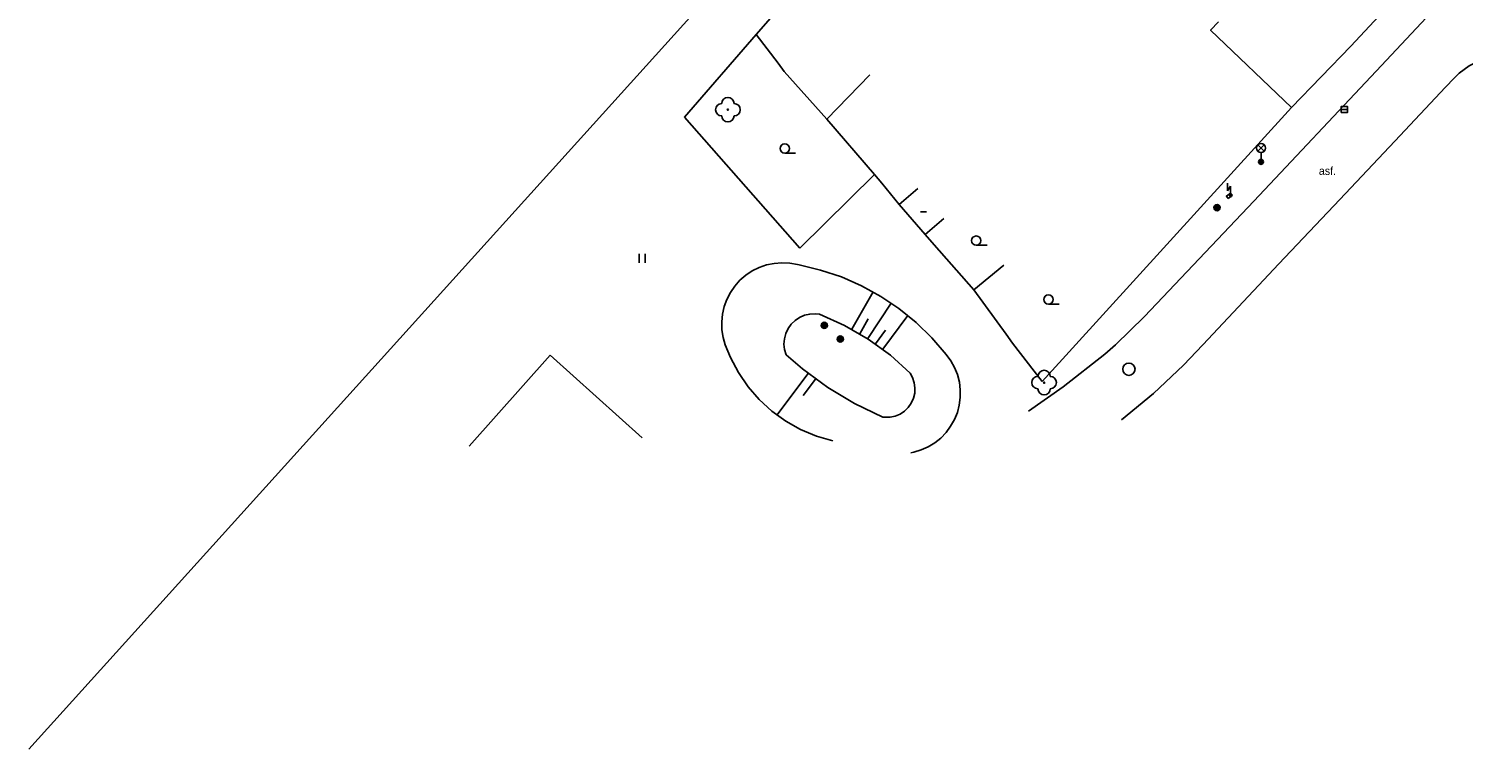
# Model space of a CAD drawing. Extents: x -539244 to -537359, y -1183785 to -1181851.
# Drawn here: x -538323 to -538206.4, y -1183785.5 to -1183727 of the extents above; entities that cross this region are included whole.
import ezdxf

# ---------------------------------------------------------------- set-up
doc = ezdxf.new("R2010")
doc.units = 0
for name, color, linetype in [('Vrstva 10', 7, 'Continuous'), ('Vrstva 14', 7, 'Continuous'), ('Vrstva 15', 7, 'Continuous'), ('Vrstva 21', 7, 'Continuous'), ('Vrstva 22', 7, 'Continuous'), ('Vrstva 24', 7, 'Continuous'), ('Vrstva 25', 7, 'Continuous'), ('Vrstva 27', 7, 'Continuous'), ('Vrstva 33', 7, 'Continuous'), ('Vrstva 36', 7, 'Continuous'), ('Vrstva 39', 7, 'Continuous'), ('Vrstva 40', 7, 'Continuous'), ('Vrstva 5', 7, 'Continuous'), ('Vrstva 7', 7, 'Continuous'), ('Vrstva 8', 7, 'Continuous')]:
    doc.layers.add(name, color=color, linetype=linetype)

msp = doc.modelspace()

# ---------------------------------------------------------------- linework, layer by layer
at = {"layer": 'Vrstva 10'}
for p, q in [((-538209.433, -1183726.06), (-538213.525, -1183730.418)), ((-538213.525, -1183730.418), (-538223.455, -1183740.964)), ((-538212.008, -1183736.103), (-538207.88, -1183731.704)), ((-538207.88, -1183731.704), (-538207.178, -1183730.974)), ((-538216.465, -1183740.837), (-538212.008, -1183736.103)), ((-538223.455, -1183740.964), (-538232.32, -1183750.334)), ((-538221.409, -1183746.068), (-538216.465, -1183740.837)), ((-538225.531, -1183750.441), (-538221.409, -1183746.068)), ((-538227.595, -1183752.627), (-538225.531, -1183750.441)), ((-538280.61, -1183753.48), (-538287.19, -1183760.86)), ((-538273.13, -1183760.2), (-538280.61, -1183753.48))]:
    msp.add_line(p, q, dxfattribs=at)
for points in [[(-538204.121, -1183729.202), (-538205.076, -1183729.521), (-538205.968, -1183729.987), (-538206.775, -1183730.588), (-538207.178, -1183730.974)], [(-538232.32, -1183750.334), (-538234.677, -1183752.637), (-538235.538, -1183753.4)], [(-538234.188, -1183758.717), (-538231.592, -1183756.593), (-538229.154, -1183754.289), (-538227.595, -1183752.627)], [(-538235.538, -1183753.4), (-538238.924, -1183756.038), (-538241.753, -1183758.022)]]:
    msp.add_lwpolyline(points, dxfattribs=at)
at = {"layer": 'Vrstva 14'}
for points in [[(-538266.38, -1183752.64), (-538266.556, -1183752.034), (-538266.655, -1183751.412), (-538266.673, -1183750.781), (-538266.612, -1183750.153), (-538266.472, -1183749.539), (-538266.256, -1183748.946), (-538265.966, -1183748.386), (-538265.608, -1183747.867), (-538265.187, -1183747.398), (-538264.71, -1183746.985), (-538264.184, -1183746.636), (-538263.619, -1183746.357), (-538263.023, -1183746.151), (-538262.405, -1183746.022), (-538261.777, -1183745.972)], [(-538261.777, -1183745.972), (-538261.147, -1183746.003), (-538260.526, -1183746.112), (-538260.38, -1183746.15)], [(-538260.38, -1183746.15), (-538258.644, -1183746.563), (-538256.952, -1183747.129), (-538255.318, -1183747.845), (-538253.754, -1183748.704), (-538252.273, -1183749.7)], [(-538261.44, -1183753.44), (-538261.566, -1183753.018), (-538261.613, -1183752.581), (-538261.58, -1183752.142), (-538261.469, -1183751.716), (-538261.283, -1183751.318), (-538261.028, -1183750.959), (-538260.712, -1183750.653), (-538260.346, -1183750.409), (-538259.942, -1183750.234), (-538259.513, -1183750.136), (-538259.073, -1183750.117), (-538258.72, -1183750.16)], [(-538258.72, -1183750.16), (-538256.687, -1183751.056), (-538254.762, -1183752.167), (-538252.968, -1183753.478), (-538251.37, -1183754.93)], [(-538252.273, -1183749.7), (-538250.888, -1183750.824), (-538249.609, -1183752.068), (-538248.446, -1183753.421), (-538248.06, -1183753.93)], [(-538265.319, -1183754.896), (-538265.967, -1183753.668), (-538266.38, -1183752.64)], [(-538253.59, -1183758.51), (-538255.881, -1183757.414), (-538258.059, -1183756.107), (-538260.103, -1183754.601), (-538261.44, -1183753.44)], [(-538248.06, -1183753.93), (-538247.755, -1183754.476), (-538247.523, -1183755.057), (-538247.366, -1183755.662), (-538247.288, -1183756.283), (-538247.289, -1183756.908), (-538247.371, -1183757.528), (-538247.531, -1183758.133), (-538247.766, -1183758.712), (-538248.074, -1183759.257), (-538248.448, -1183759.757), (-538248.883, -1183760.207), (-538249.372, -1183760.596), (-538249.907, -1183760.921), (-538250.479, -1183761.174), (-538251.078, -1183761.353), (-538251.31, -1183761.4)], [(-538257.64, -1183760.43), (-538258.975, -1183760.048), (-538260.257, -1183759.515), (-538261.47, -1183758.838), (-538262.596, -1183758.026), (-538263.622, -1183757.09), (-538264.534, -1183756.042), (-538265.319, -1183754.896)], [(-538251.37, -1183754.93), (-538251.162, -1183755.305), (-538251.028, -1183755.712), (-538250.971, -1183756.137), (-538250.994, -1183756.566), (-538251.096, -1183756.982), (-538251.273, -1183757.372), (-538251.52, -1183757.723), (-538251.827, -1183758.022), (-538252.185, -1183758.259), (-538252.58, -1183758.425), (-538252.999, -1183758.516), (-538253.428, -1183758.527), (-538253.59, -1183758.51)]]:
    msp.add_lwpolyline(points, dxfattribs=at)
at = {"layer": 'Vrstva 15'}
for p, q in [((-538256.099, -1183751.366), (-538254.378, -1183748.339)), ((-538254.811, -1183752.135), (-538252.918, -1183749.242)), ((-538255.448, -1183751.739), (-538254.761, -1183750.531)), ((-538253.583, -1183752.995), (-538251.544, -1183750.266)), ((-538254.189, -1183752.554), (-538253.367, -1183751.454)), ((-538259.641, -1183754.969), (-538262.18, -1183758.349)), ((-538259.042, -1183755.42), (-538260.05, -1183756.763))]:
    msp.add_line(p, q, dxfattribs=at)
at = {"layer": 'Vrstva 21'}
for p, q in [((-538263.86, -1183727.43), (-538269.69, -1183734.15)), ((-538269.69, -1183734.15), (-538260.33, -1183744.79)), ((-538260.33, -1183744.79), (-538254.26, -1183738.8))]:
    msp.add_line(p, q, dxfattribs=at)
at = {"layer": 'Vrstva 22'}
for centre in [(-538266.17, -1183733.54), (-538240.48, -1183755.71)]:
    msp.add_circle(centre, 0.05, dxfattribs=at)
for centre, start, end in [((-538266.67, -1183733.54), 90, 270), ((-538266.17, -1183733.04), 0, 180), ((-538265.67, -1183733.54), 270, 90), ((-538266.17, -1183734.04), 180, 0), ((-538240.98, -1183755.71), 90, 270), ((-538240.48, -1183755.21), 0, 180), ((-538239.98, -1183755.71), 270, 90), ((-538240.48, -1183756.21), 180, 0)]:
    msp.add_arc(centre, 0.5, start, end, dxfattribs=at)
at = {"layer": 'Vrstva 24'}
for p, q in [((-538225.581, -1183739.509), (-538225.581, -1183740.135)), ((-538225.581, -1183740.135), (-538225.331, -1183739.76)), ((-538225.331, -1183739.76), (-538225.331, -1183740.635)), ((-538225.441, -1183740.39), (-538225.331, -1183740.635)), ((-538225.331, -1183740.635), (-538225.221, -1183740.39))]:
    msp.add_line(p, q, dxfattribs=at)
msp.add_lwpolyline([(-538225.53, -1183740.75), (-538225.673, -1183740.56), (-538225.343, -1183740.31), (-538225.2, -1183740.5), (-538225.53, -1183740.75)], dxfattribs=at)
at = {"layer": 'Vrstva 25'}
for centre, radius in [((-538226.437, -1183741.494), 0.25), ((-538226.437, -1183741.494), 0.2), ((-538226.437, -1183741.494), 0.15), ((-538226.437, -1183741.494), 0.1), ((-538226.437, -1183741.494), 0.05), ((-538258.34, -1183751.06), 0.25), ((-538258.34, -1183751.06), 0.2), ((-538258.34, -1183751.06), 0.15), ((-538258.34, -1183751.06), 0.1), ((-538258.34, -1183751.06), 0.05), ((-538257.04, -1183752.17), 0.25), ((-538257.04, -1183752.17), 0.2), ((-538257.04, -1183752.17), 0.15), ((-538257.04, -1183752.17), 0.1), ((-538257.04, -1183752.17), 0.05)]:
    msp.add_circle(centre, radius, dxfattribs=at)
at = {"layer": 'Vrstva 27'}
msp.add_line((-538216.349, -1183733.524), (-538215.849, -1183733.524), dxfattribs=at)
msp.add_lwpolyline([(-538216.349, -1183733.774), (-538215.849, -1183733.774), (-538215.849, -1183733.274), (-538216.349, -1183733.274)], close=True, dxfattribs=at)
msp.add_circle((-538233.598, -1183754.62), 0.5, dxfattribs=at)
at = {"layer": 'Vrstva 33'}
for p, q in [((-538223.129, -1183736.921), (-538222.599, -1183736.391)), ((-538223.129, -1183736.391), (-538222.599, -1183736.921)), ((-538222.864, -1183737.031), (-538222.864, -1183737.781))]:
    msp.add_line(p, q, dxfattribs=at)
for centre, radius in [((-538222.864, -1183736.656), 0.375), ((-538222.864, -1183737.781), 0.2), ((-538222.864, -1183737.781), 0.145), ((-538222.864, -1183737.781), 0.0876)]:
    msp.add_circle(centre, radius, dxfattribs=at)
at = {"layer": 'Vrstva 36'}
for p, q in [((-538261.548, -1183737.067), (-538260.673, -1183737.067)), ((-538245.996, -1183744.548), (-538245.121, -1183744.548)), ((-538273.376, -1183745.991), (-538273.376, -1183745.241)), ((-538272.876, -1183745.991), (-538272.876, -1183745.241)), ((-538240.133, -1183749.33), (-538239.258, -1183749.33))]:
    msp.add_line(p, q, dxfattribs=at)
for centre in [(-538261.548, -1183736.692), (-538245.996, -1183744.173), (-538240.133, -1183748.955)]:
    msp.add_circle(centre, 0.375, dxfattribs=at)
at = {"layer": 'Vrstva 39'}
msp.add_line((-538250.528, -1183741.824), (-538250.028, -1183741.824), dxfattribs=at)
at = {"layer": 'Vrstva 5'}
for p, q in [((-538215.568, -1183728.37), (-538212.15, -1183724.72)), ((-538220.4, -1183733.36), (-538215.568, -1183728.37)), ((-538252.25, -1183741.24), (-538250.734, -1183739.935)), ((-538252.25, -1183741.24), (-538250.15, -1183743.68)), ((-538250.15, -1183743.68), (-538248.634, -1183742.375))]:
    msp.add_line(p, q, dxfattribs=at)
msp.add_lwpolyline([(-538226.32, -1183726.41), (-538226.96, -1183727.09), (-538220.4, -1183733.36)], dxfattribs=at)
at = {"layer": 'Vrstva 7'}
for p, q in [((-538263.86, -1183727.43), (-538256.2, -1183718.61)), ((-538322.96, -1183785.49), (-538267.21, -1183723.77)), ((-538262.08, -1183729.76), (-538263.86, -1183727.43)), ((-538258.12, -1183734.31), (-538261.61, -1183730.45)), ((-538258.12, -1183734.31), (-538254.639, -1183730.721)), ((-538254.26, -1183738.8), (-538258.12, -1183734.31)), ((-538220.4, -1183733.36), (-538240.651, -1183755.61)), ((-538252.25, -1183741.24), (-538253.66, -1183739.52)), ((-538249.42, -1183744.53), (-538246.18, -1183748.17)), ((-538246.18, -1183748.17), (-538243.743, -1183746.175)), ((-538246.18, -1183748.17), (-538243.56, -1183751.78)), ((-538240.651, -1183755.61), (-538243.04, -1183752.5))]:
    msp.add_line(p, q, dxfattribs=at)
at = {"layer": 'Vrstva 8'}
for p, q in [((-538262.08, -1183729.76), (-538261.61, -1183730.45)), ((-538254.26, -1183738.8), (-538253.66, -1183739.52)), ((-538249.42, -1183744.53), (-538250.15, -1183743.68)), ((-538243.04, -1183752.5), (-538243.56, -1183751.78))]:
    msp.add_line(p, q, dxfattribs=at)

# ---------------------------------------------------------------- texts
at = {"layer": 'Vrstva 40'}
msp.add_text('asf.', height=0.65, dxfattribs=at).set_placement((-538218.166, -1183738.835))

doc.saveas('drawing.dxf')
